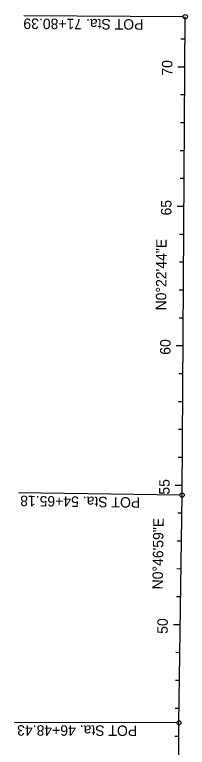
# Model space of a CAD drawing. Extents: x 1280727 to 1452510, y 526233 to 601451.
# Drawn here: x 1424633 to 1425252, y 586951 to 589578 of the extents above; entities that cross this region are included whole.
import ezdxf

# ---------------------------------------------------------------- set-up
doc = ezdxf.new("R2010")
doc.units = 0
for name, color, linetype in [('RW_X_CL', 7, 'Continuous'), ('RW_X_CL_500_Stations', 7, 'Continuous'), ('SH_Text', 7, 'Continuous')]:
    doc.layers.add(name, color=color, linetype=linetype)

msp = doc.modelspace()

# ---------------------------------------------------------------- linework, layer by layer
at = {"layer": 'RW_X_CL'}
for p, q in [((1425233.6, 587855.2), (1425244.9, 589570.3)), ((1425222.4, 587038.5), (1425233.6, 587855.2)), ((1425214.7, 584440.3), (1425222.4, 587038.5))]:
    msp.add_line(p, q, dxfattribs=at)
at = {"layer": 'RW_X_CL_500_Stations'}
for p, q in [((1425244.4, 589489.9), (1425229.4, 589490)), ((1425243.8, 589389.9), (1425218.8, 589390.1)), ((1425243.1, 589290), (1425228.1, 589290.1)), ((1425242.4, 589190), (1425227.4, 589190.1)), ((1425241.8, 589090), (1425226.8, 589090.1)), ((1425241.1, 588990), (1425226.1, 588990.1)), ((1425240.4, 588890), (1425215.4, 588890.1)), ((1425239.8, 588790), (1425224.8, 588790.1)), ((1425239.1, 588690), (1425224.1, 588690.1)), ((1425238.5, 588590), (1425223.5, 588590.1)), ((1425237.8, 588490), (1425222.8, 588490.1)), ((1425237.1, 588390), (1425212.1, 588390.1)), ((1425236.5, 588290), (1425221.5, 588290.1)), ((1425235.8, 588190), (1425220.8, 588190.1)), ((1425235.2, 588090), (1425220.2, 588090.1)), ((1425234.5, 587990), (1425219.5, 587990.1)), ((1425233.8, 587890), (1425208.8, 587890.1)), ((1425232.7, 587790), (1425217.7, 587790.2)), ((1425231.3, 587690), (1425216.3, 587690.2)), ((1425230, 587590), (1425215, 587590.2)), ((1425228.6, 587490), (1425213.6, 587490.2)), ((1425227.2, 587390), (1425202.2, 587390.4)), ((1425225.9, 587290), (1425210.9, 587290.2)), ((1425224.5, 587190), (1425209.5, 587190.2)), ((1425223.1, 587090.1), (1425208.1, 587090.3)), ((1425222.3, 586990.1), (1425207.3, 586990.1))]:
    msp.add_line(p, q, dxfattribs=at)
at = {"layer": 'SH_Text'}
for p, q in [((1425237.4, 589570.4), (1424665.2, 589574.2)), ((1425226.1, 587855.3), (1424646.8, 587863.2)), ((1425214.9, 587038.5), (1424632.6, 587040.2))]:
    msp.add_line(p, q, dxfattribs=at)
for centre in [(1425244.9, 589570.3), (1425233.6, 587855.2), (1425222.4, 587038.5)]:
    msp.add_circle(centre, 7.5, dxfattribs=at)

# ---------------------------------------------------------------- texts
at = {"layer": 'RW_X_CL_500_Stations'}
for s, rotation, p in [('70', 89.621, (1425198.5, 589358.9)), ('65', 89.621, (1425195.2, 588857.6)), ('60', 89.621, (1425191.9, 588358.1)), ('55', 89.621, (1425188.6, 587856.6)), ('50', 89.217, (1425181.8, 587357.4))]:
    msp.add_text(s, height=37.5, rotation=rotation, dxfattribs=at).set_placement(p)
at = {"layer": 'SH_Text'}
for s, rotation, p in [('POT Sta. 71+80.39', 179.621, (1425094.9, 589561.3)), ('N0°22\'44"E', 89.621, (1425176.5, 588517.2)), ('POT Sta. 54+65.18', 179.217, (1425083.5, 587847.2)), ('N0°46\'59"E', 89.217, (1425164.1, 587516.6)), ('POT Sta. 46+48.43', 179.8291, (1425072.4, 587028.9))]:
    msp.add_text(s, height=37.5, rotation=rotation, dxfattribs=at).set_placement(p)

doc.saveas('drawing.dxf')
